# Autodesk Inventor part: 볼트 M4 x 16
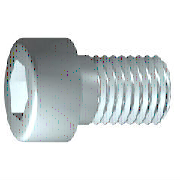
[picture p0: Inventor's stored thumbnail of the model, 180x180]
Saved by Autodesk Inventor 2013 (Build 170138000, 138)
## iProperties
Created: 2012-02
Part Number: 볼트 M4 x 16
Material: 스테인리스강
Description: 6각 소켓 머리 캡 나사
Document SubType Name: Modeling
Standard: ISO 4762
Designer: mduedu
Standard Revision: Fourth edition 2004-03-01
Standards Organization: ISO
Language: ko-KR
Size Designation: M4 x 16
Categories: <MemberInstance><Categories><Category DisplayName="조임쇠" InternalName="e4da775c-781d-43d5-af7c-5136215cf5a6" Mnemonic="FSTN"><Category DisplayName="볼트" InternalN
Density: 8.08 g/cm^3
Mass: 2.70334 g
Surface Area: 3.81118 cm^2
Volume: 0.334572 cm^3
IsCustomPart: 0
Author: mduedu
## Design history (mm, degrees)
sketch "스케치1"
  geometry: L1 (-1, 0)-(16, 0); L2 (16, 0)-(16, 2); L3 (16, 2)-(1.75, 2); L4 (1.75, 2)-(1.32, 2); L5 (1.32, 2)-(0, 2); L6 (0, 2)-(0, 3.5); L7 (0, 3.5)-(-4, 3.5); L8 (-4, 3.5)-(-4, 1.732); L9 (-4, 1.732)-(-2, 1.732); L10 (-2, 1.732)-(-1, 0); L11 (-8, 0)-(20, 0) reference; L12 (0, -0.7)-(0, 4.2) reference; L13 (1.75, 2)-(0, 2)
  constraints: 22 end point, 6 parallel, 2 collinear, 2 perpendicular, 1 horizontal, 1 point on line
  dimensions: "d1" = 14.25 distance from line of L3.end L2 (= GEL); "d2" = 0.42952 distance of L4.end L3.end (computed from GAL); "d3" = 4 distance between parallel lines of L8 L6 (= KOH); "d4" = 2 distance of L8.end L9.end (= INTI); "d5" = 60 deg angle of L10 L1; "d6" = 4 diameter of L3 L1 (= GD); "d7" = 4 diameter of L5 L1 (= BDM); "d8" = 3.4641 diameter of L9 L1 (= 1.1547 x SW); "d9" = 7 diameter of L7 L1 (= KOD); "d26" = 16 distance between parallel lines of L12 L2 (= NLG)
revolve "본체" sketch "스케치1" stored, may be unused: angle "d10" = 90 deg
sketch "스케치2"
  geometry: L1 (0, -4.9)-(0, 4.9) reference; L2 (-4.9, 0)-(4.9, 0) reference; L3 (1.732, 0)-(0.866, -1.5); L4 (0.866, -1.5)-(-0.866, -1.5); L5 (-0.866, -1.5)-(-1.732, 0); L6 (-1.732, 0)-(-0.866, 1.5); L7 (-0.866, 1.5)-(0.866, 1.5); L8 (0.866, 1.5)-(1.732, 0); 2 further points
  constraints: 12 end point, 1 coincident, 1 horizontal alignment, 1 point on line, 12 other
extrude "슬롯" join sketch "스케치2" stored distance "d11" = 10; taper "d12" = 0 deg
workplane "Work Plane1"
fillet "Fillet2" dims "d30" = 0.1 (= R)
body "Solid1"
fillet "모깎기1" dims "d17" = 0.4 (= RR)
feature "스레드" dims "d13" = 14.25 (= GEL), "d14" = 0
chamfer "모따기1" distance "d15" = 0.42941 (= -0.5 x SPD + 0.5 x GD); stored, may be unused: second distance "d16" = 0.42941 (= GUL), angle "d27" = 45 deg
other parameters: "GD" = 4 [user parameter; used in 2 equation terms], "NLG" = 16 [user parameter; used in 1 equation term], "GEL" = 14.25 [user parameter; used in 2 equation terms], "KOD" = 7 [user parameter; used in 1 equation term], "KOH" = 4 [user parameter; used in 1 equation term], "INTI" = 2 [user parameter; used in 1 equation term], "GAL" = 0.42941 (= 0.61345 x PTC) [user parameter; used in 1 equation term], "GUL" = 0.42941 (= 0.61345 x PTC) [user parameter; used in 1 equation term], "BDM" = 4 (= NND) [user parameter; used in 1 equation term], "SW" = 3 [user parameter; used in 2 equation terms], "RR" = 0.4 [user parameter; used in 1 equation term], "SPD" = 3.14117 (= NND - 1.2269 x PTC) [user parameter; used in 1 equation term], "d19" = 0, "d28" = 0, "d29" = 0, "R" = 0.1 [user parameter; used in 1 equation term], "TOA" = 30 deg [user parameter], "GD1" = 3.14117 (= THREADDIA - 1.2269 x PTC) [user parameter], "THREADDIA" = 4 [user parameter; used in 1 equation term], "FAWI" = 45 deg [user parameter], "TPU" = 14.28571 (computed from PTC) [user parameter], "PTC" = 0.7 [user parameter; used in 5 equation terms], "NND" = 4 [user parameter; used in 2 equation terms], "E0" = 3.465 (= 1.155 x SW) [user parameter]
